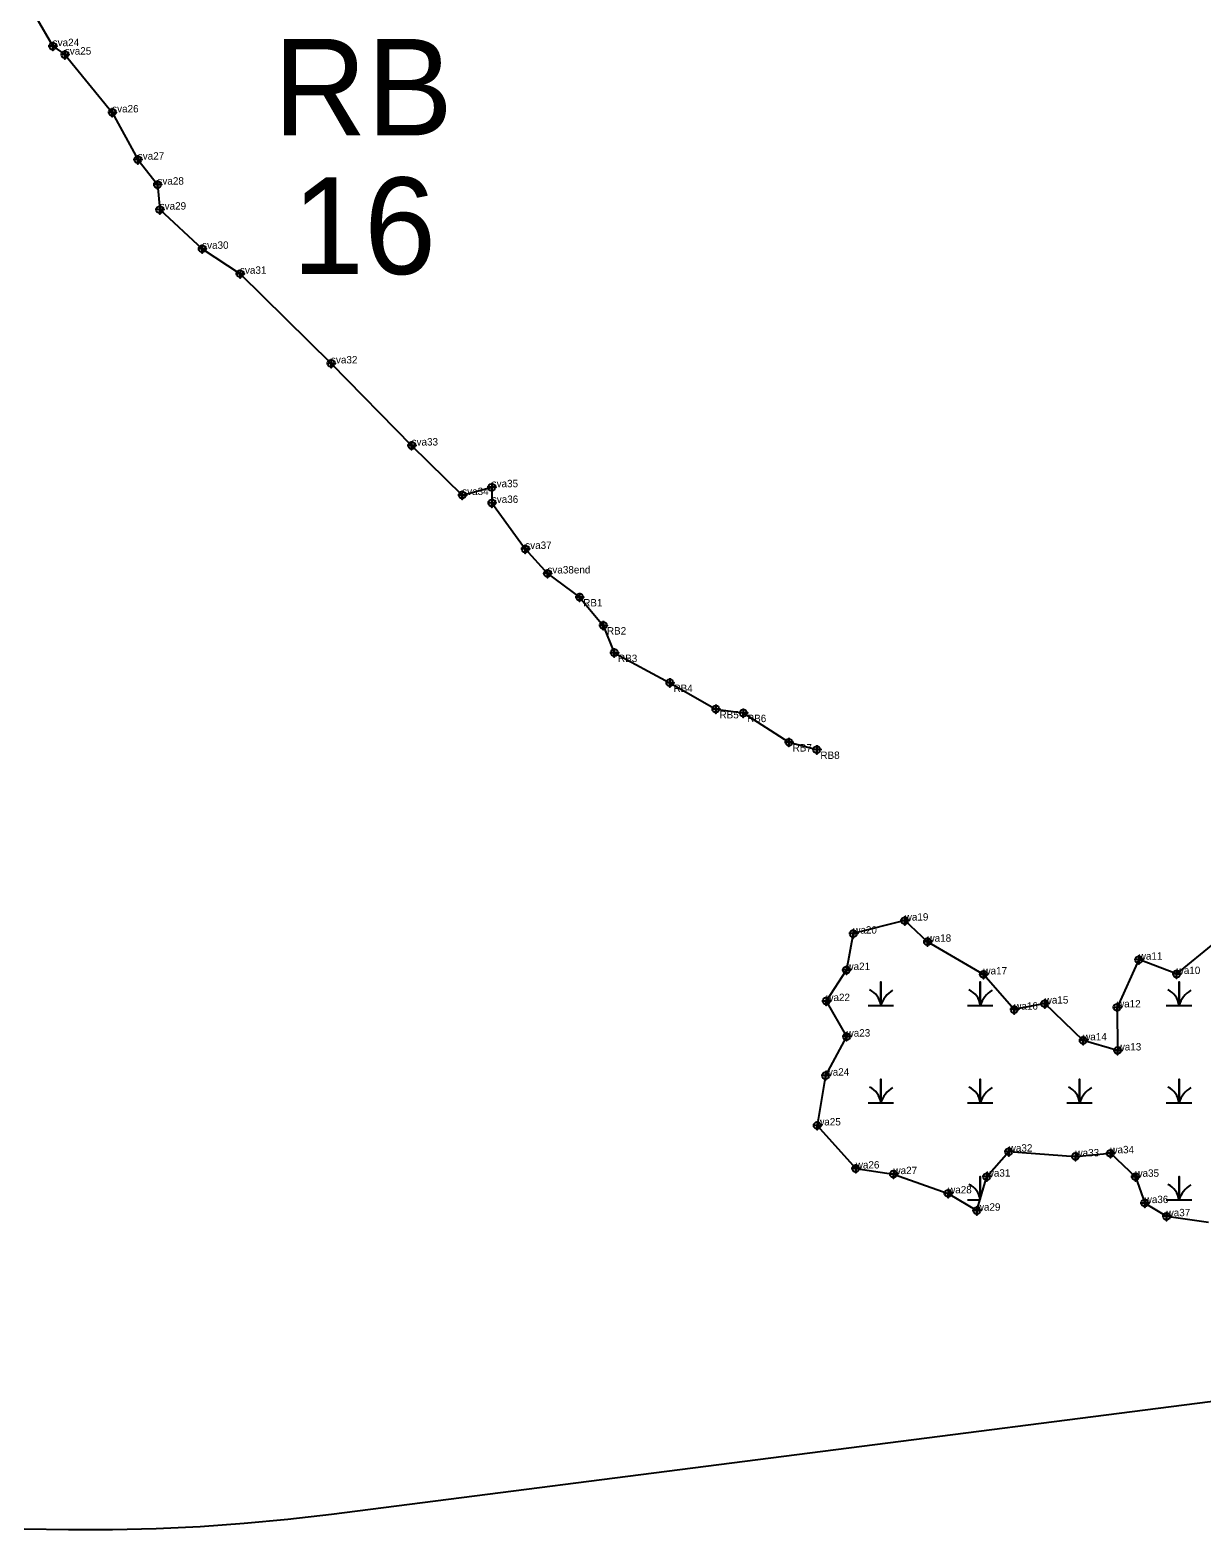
# Model space of a CAD drawing. Extents: x 2071991 to 2268989, y 436479 to 469629.
# Drawn here: x 2212061 to 2212853, y 439006 to 440020 of the extents above; entities that cross this region are included whole.
import ezdxf

# ---------------------------------------------------------------- set-up
doc = ezdxf.new("R2010")
doc.units = 0
for name, color, linetype in [('approx_PSA', 7, 'Continuous'), ('Default', 7, 'Continuous'), ('Exist Environmental Wetland Boundary', 7, 'Continuous'), ('Exist Environmental Wetland Boundary Cogo Comment', 7, 'Continuous'), ('Exist Environmental Wetland Boundary Cogo Point CELL', 7, 'Continuous'), ('Exist Hydro Jurisdictional Stream or Body of Water NEU Mitigable', 7, 'Continuous'), ('Exist Hydro Jurisdictional Stream or Body of Water NEU Mitigable Cogo Comment', 7, 'Continuous'), ('Exist Hydro Jurisdictional Stream or Body of Water NEU Mitigable Cogo Point CELL', 7, 'Continuous'), ('Exist Hydro Swamp or Marsh', 7, 'Continuous')]:
    doc.layers.add(name, color=color, linetype=linetype)

msp = doc.modelspace()

# ---------------------------------------------------------------- linework, layer by layer
at = {"layer": 'approx_PSA'}
for p, q in [((2212901.9, 439098.2), (2212264.6, 439016.5)), ((2212235.1, 439013), (2212205.5, 439010.3)), ((2212264.6, 439016.5), (2212235.1, 439013)), ((2212086.7, 439006), (2212056.9, 439006.6)), ((2212116.4, 439006), (2212086.7, 439006)), ((2212146.1, 439006.8), (2212116.4, 439006)), ((2212175.8, 439008.2), (2212146.1, 439006.8)), ((2212205.5, 439010.3), (2212175.8, 439008.2))]:
    msp.add_line(p, q, dxfattribs=at)
at = {"layer": 'Exist Environmental Wetland Boundary'}
msp.add_lwpolyline([(2212861.6, 439403.2), (2212835.8, 439381.9), (2212810.2, 439391.6), (2212795.5, 439359.3), (2212795.9, 439330.2), (2212772.6, 439337), (2212746.6, 439361.9), (2212726, 439357.8), (2212705.2, 439381.6), (2212667.4, 439403.7), (2212652, 439418), (2212617.2, 439409.2), (2212612.6, 439384.6), (2212599, 439363.6), (2212612.7, 439339.6), (2212598.5, 439313.2), (2212592.8, 439279.5), (2212618.9, 439250.4), (2212644.4, 439246.6), (2212681.3, 439233.6), (2212700.7, 439221.9), (2212707.4, 439244.9), (2212722.3, 439261.8), (2212767.4, 439258.6), (2212791, 439260.7), (2212807.9, 439244.8), (2212814.2, 439227), (2212829, 439218.1), (2212857.3, 439214.2)], dxfattribs=at)
at = {"layer": 'Exist Environmental Wetland Boundary Cogo Point CELL'}
for points in [[(2212652, 439421), (2212652, 439415), (2212652, 439418), (2212655, 439418), (2212649, 439418)], [(2212617.2, 439412.2), (2212617.2, 439406.2), (2212617.2, 439409.2), (2212620.2, 439409.2), (2212614.2, 439409.2)], [(2212667.4, 439406.7), (2212667.4, 439400.7), (2212667.4, 439403.7), (2212670.4, 439403.7), (2212664.4, 439403.7)], [(2212612.6, 439387.6), (2212612.6, 439381.6), (2212612.6, 439384.6), (2212615.6, 439384.6), (2212609.6, 439384.6)], [(2212810.2, 439394.6), (2212810.2, 439388.6), (2212810.2, 439391.6), (2212813.2, 439391.6), (2212807.2, 439391.6)], [(2212705.2, 439384.6), (2212705.2, 439378.6), (2212705.2, 439381.6), (2212708.2, 439381.6), (2212702.2, 439381.6)], [(2212835.8, 439384.9), (2212835.8, 439378.9), (2212835.8, 439381.9), (2212838.8, 439381.9), (2212832.8, 439381.9)], [(2212599, 439366.6), (2212599, 439360.6), (2212599, 439363.6), (2212602, 439363.6), (2212596, 439363.6)], [(2212726, 439360.8), (2212726, 439354.8), (2212726, 439357.8), (2212729, 439357.8), (2212723, 439357.8)], [(2212746.6, 439364.9), (2212746.6, 439358.9), (2212746.6, 439361.9), (2212749.6, 439361.9), (2212743.6, 439361.9)], [(2212795.5, 439362.3), (2212795.5, 439356.3), (2212795.5, 439359.3), (2212798.5, 439359.3), (2212792.5, 439359.3)], [(2212612.7, 439342.6), (2212612.7, 439336.6), (2212612.7, 439339.6), (2212615.7, 439339.6), (2212609.7, 439339.6)], [(2212772.6, 439340), (2212772.6, 439334), (2212772.6, 439337), (2212775.6, 439337), (2212769.6, 439337)], [(2212795.9, 439333.2), (2212795.9, 439327.2), (2212795.9, 439330.2), (2212798.9, 439330.2), (2212792.9, 439330.2)], [(2212598.5, 439316.2), (2212598.5, 439310.2), (2212598.5, 439313.2), (2212601.5, 439313.2), (2212595.5, 439313.2)], [(2212592.8, 439282.5), (2212592.8, 439276.5), (2212592.8, 439279.5), (2212595.8, 439279.5), (2212589.8, 439279.5)], [(2212722.3, 439264.8), (2212722.3, 439258.8), (2212722.3, 439261.8), (2212725.3, 439261.8), (2212719.3, 439261.8)], [(2212767.4, 439261.6), (2212767.4, 439255.6), (2212767.4, 439258.6), (2212770.4, 439258.6), (2212764.4, 439258.6)], [(2212791, 439263.7), (2212791, 439257.7), (2212791, 439260.7), (2212794, 439260.7), (2212788, 439260.7)], [(2212618.9, 439253.4), (2212618.9, 439247.4), (2212618.9, 439250.4), (2212621.9, 439250.4), (2212615.9, 439250.4)], [(2212644.4, 439249.6), (2212644.4, 439243.6), (2212644.4, 439246.6), (2212647.4, 439246.6), (2212641.4, 439246.6)], [(2212707.4, 439247.9), (2212707.4, 439241.9), (2212707.4, 439244.9), (2212710.4, 439244.9), (2212704.4, 439244.9)], [(2212807.9, 439247.8), (2212807.9, 439241.8), (2212807.9, 439244.8), (2212810.9, 439244.8), (2212804.9, 439244.8)], [(2212681.3, 439236.6), (2212681.3, 439230.6), (2212681.3, 439233.6), (2212684.3, 439233.6), (2212678.3, 439233.6)], [(2212700.7, 439224.9), (2212700.7, 439218.9), (2212700.7, 439221.9), (2212703.7, 439221.9), (2212697.7, 439221.9)], [(2212814.2, 439230), (2212814.2, 439224), (2212814.2, 439227), (2212817.2, 439227), (2212811.2, 439227)], [(2212829, 439221.1), (2212829, 439215.1), (2212829, 439218.1), (2212832, 439218.1), (2212826, 439218.1)]]:
    msp.add_lwpolyline(points, dxfattribs=at)
for centre in [(2212652, 439418), (2212617.2, 439409.2), (2212667.4, 439403.7), (2212612.6, 439384.6), (2212810.2, 439391.6), (2212705.2, 439381.6), (2212835.8, 439381.9), (2212599, 439363.6), (2212726, 439357.8), (2212746.6, 439361.9), (2212795.5, 439359.3), (2212612.7, 439339.6), (2212772.6, 439337), (2212795.9, 439330.2), (2212598.5, 439313.2), (2212592.8, 439279.5), (2212722.3, 439261.8), (2212767.4, 439258.6), (2212791, 439260.7), (2212618.9, 439250.4), (2212644.4, 439246.6), (2212707.4, 439244.9), (2212807.9, 439244.8), (2212681.3, 439233.6), (2212700.7, 439221.9), (2212814.2, 439227), (2212829, 439218.1)]:
    msp.add_circle(centre, 2.34, dxfattribs=at)
at = {"layer": 'Exist Hydro Jurisdictional Stream or Body of Water NEU Mitigable'}
for points in [[(2212064.6, 440029), (2212076.1, 440009.2), (2212084.3, 440003.5), (2212116.3, 439964.4), (2212133.6, 439932.5), (2212146.9, 439915.6), (2212148.4, 439898.7), (2212177.1, 439872.2), (2212202.7, 439855.3), (2212264.2, 439794.7), (2212318.7, 439739.2), (2212352.9, 439705.7), (2212372.8, 439711), (2212372.9, 439700.4), (2212395.5, 439669.3), (2212410.5, 439652.7)], [(2212410.5, 439652.7), (2212432.2, 439636.7), (2212448.2, 439617.6), (2212455.7, 439599.1), (2212493.2, 439578.8), (2212524.3, 439561), (2212542.9, 439558.4), (2212573.7, 439538.6), (2212592.5, 439533.6)]]:
    msp.add_lwpolyline(points, dxfattribs=at)
at = {"layer": 'Exist Hydro Jurisdictional Stream or Body of Water NEU Mitigable Cogo Point CELL'}
for points in [[(2212076.1, 440012.2), (2212076.1, 440006.2), (2212076.1, 440009.2), (2212079.1, 440009.2), (2212073.1, 440009.2)], [(2212084.3, 440006.5), (2212084.3, 440000.5), (2212084.3, 440003.5), (2212087.3, 440003.5), (2212081.3, 440003.5)], [(2212116.3, 439967.4), (2212116.3, 439961.4), (2212116.3, 439964.4), (2212119.3, 439964.4), (2212113.3, 439964.4)], [(2212133.6, 439935.5), (2212133.6, 439929.5), (2212133.6, 439932.5), (2212136.6, 439932.5), (2212130.6, 439932.5)], [(2212146.9, 439918.6), (2212146.9, 439912.6), (2212146.9, 439915.6), (2212149.9, 439915.6), (2212143.9, 439915.6)], [(2212148.4, 439901.7), (2212148.4, 439895.7), (2212148.4, 439898.7), (2212151.4, 439898.7), (2212145.4, 439898.7)], [(2212177.1, 439875.2), (2212177.1, 439869.2), (2212177.1, 439872.2), (2212180.1, 439872.2), (2212174.1, 439872.2)], [(2212202.7, 439858.3), (2212202.7, 439852.3), (2212202.7, 439855.3), (2212205.7, 439855.3), (2212199.7, 439855.3)], [(2212264.2, 439797.7), (2212264.2, 439791.7), (2212264.2, 439794.7), (2212267.2, 439794.7), (2212261.2, 439794.7)], [(2212318.7, 439742.2), (2212318.7, 439736.2), (2212318.7, 439739.2), (2212321.7, 439739.2), (2212315.7, 439739.2)], [(2212372.8, 439714), (2212372.8, 439708), (2212372.8, 439711), (2212375.8, 439711), (2212369.8, 439711)], [(2212352.9, 439708.7), (2212352.9, 439702.7), (2212352.9, 439705.7), (2212355.9, 439705.7), (2212349.9, 439705.7)], [(2212372.9, 439703.4), (2212372.9, 439697.4), (2212372.9, 439700.4), (2212375.9, 439700.4), (2212369.9, 439700.4)], [(2212395.5, 439672.3), (2212395.5, 439666.3), (2212395.5, 439669.3), (2212398.5, 439669.3), (2212392.5, 439669.3)], [(2212410.5, 439655.7), (2212410.5, 439649.7), (2212410.5, 439652.7), (2212413.5, 439652.7), (2212407.5, 439652.7)], [(2212432.2, 439639.7), (2212432.2, 439633.7), (2212432.2, 439636.7), (2212435.2, 439636.7), (2212429.2, 439636.7)], [(2212448.2, 439620.6), (2212448.2, 439614.6), (2212448.2, 439617.6), (2212451.2, 439617.6), (2212445.2, 439617.6)], [(2212455.7, 439602.1), (2212455.7, 439596.1), (2212455.7, 439599.1), (2212458.7, 439599.1), (2212452.7, 439599.1)], [(2212493.2, 439581.8), (2212493.2, 439575.8), (2212493.2, 439578.8), (2212496.2, 439578.8), (2212490.2, 439578.8)], [(2212524.3, 439564), (2212524.3, 439558), (2212524.3, 439561), (2212527.3, 439561), (2212521.3, 439561)], [(2212542.9, 439561.4), (2212542.9, 439555.4), (2212542.9, 439558.4), (2212545.9, 439558.4), (2212539.9, 439558.4)], [(2212573.7, 439541.6), (2212573.7, 439535.6), (2212573.7, 439538.6), (2212576.7, 439538.6), (2212570.7, 439538.6)], [(2212592.5, 439536.6), (2212592.5, 439530.6), (2212592.5, 439533.6), (2212595.5, 439533.6), (2212589.5, 439533.6)]]:
    msp.add_lwpolyline(points, dxfattribs=at)
for centre in [(2212076.1, 440009.2), (2212084.3, 440003.5), (2212116.3, 439964.4), (2212133.6, 439932.5), (2212146.9, 439915.6), (2212148.4, 439898.7), (2212177.1, 439872.2), (2212202.7, 439855.3), (2212264.2, 439794.7), (2212318.7, 439739.2), (2212372.8, 439711), (2212352.9, 439705.7), (2212372.9, 439700.4), (2212395.5, 439669.3), (2212410.5, 439652.7), (2212432.2, 439636.7), (2212448.2, 439617.6), (2212455.7, 439599.1), (2212493.2, 439578.8), (2212524.3, 439561), (2212542.9, 439558.4), (2212573.7, 439538.6), (2212592.5, 439533.6)]:
    msp.add_circle(centre, 2.34, dxfattribs=at)
at = {"layer": 'Exist Hydro Swamp or Marsh'}
msp.add_line((2212694.4, 439229.1), (2212702.8, 439229.1), dxfattribs=at)
for points in [[(2212627.2, 439360.7), (2212635.8, 439360.7), (2212635.8, 439376.5), (2212635.8, 439360.7), (2212644.4, 439360.7)], [(2212694.4, 439360.7), (2212703, 439360.7), (2212703, 439376.5), (2212703, 439360.7), (2212711.6, 439360.7)], [(2212828.8, 439360.7), (2212837.4, 439360.7), (2212837.4, 439376.5), (2212837.4, 439360.7), (2212846, 439360.7)], [(2212627.2, 439294.9), (2212635.8, 439294.9), (2212635.8, 439310.7), (2212635.8, 439294.9), (2212644.4, 439294.9)], [(2212694.4, 439294.9), (2212703, 439294.9), (2212703, 439310.7), (2212703, 439294.9), (2212711.6, 439294.9)], [(2212761.6, 439294.9), (2212770.2, 439294.9), (2212770.2, 439310.7), (2212770.2, 439294.9), (2212778.8, 439294.9)], [(2212828.8, 439294.9), (2212837.4, 439294.9), (2212837.4, 439310.7), (2212837.4, 439294.9), (2212846, 439294.9)], [(2212703, 439229.7), (2212703, 439244.9), (2212703, 439229.7)], [(2212828.8, 439229.1), (2212837.4, 439229.1), (2212837.4, 439244.9), (2212837.4, 439229.1), (2212846, 439229.1)]]:
    msp.add_lwpolyline(points, dxfattribs=at)
for centre, radius, start, end in [((2212623.5, 439359.8), 12.3, 4.1403, 67.535), ((2212654, 439354.6), 19.2, 122.1274, 161.6222), ((2212690.7, 439359.8), 12.3, 4.1403, 67.535), ((2212721.2, 439354.6), 19.2, 122.1274, 161.6222), ((2212825.1, 439359.8), 12.3, 4.1403, 67.535), ((2212855.6, 439354.6), 19.2, 122.1274, 161.6222), ((2212623.5, 439294), 12.3, 4.1403, 67.535), ((2212690.7, 439294), 12.3, 4.1403, 67.535), ((2212757.9, 439294), 12.3, 4.1403, 67.535), ((2212825.1, 439294), 12.3, 4.1403, 67.535), ((2212654, 439288.8), 19.2, 122.1274, 161.6222), ((2212721.2, 439288.8), 19.2, 122.1274, 161.6222), ((2212788.4, 439288.8), 19.2, 122.1274, 161.6222), ((2212855.6, 439288.8), 19.2, 122.1274, 161.6222), ((2212690.7, 439228.2), 12.3, 6.2272, 67.535), ((2212825.1, 439228.2), 12.3, 4.1403, 67.535), ((2212855.6, 439223.1), 19.2, 122.1274, 161.6222)]:
    msp.add_arc(centre, radius, start, end, dxfattribs=at)

# ---------------------------------------------------------------- texts
at = {"layer": 'Default'}
for s, p in [('RB', (2212225.2, 439948.8)), ('RB', (2212225.2, 439948.8)), ('16', (2212238, 439855.1))]:
    msp.add_text(s, height=65.34, dxfattribs=at).set_placement(p)
at = {"layer": 'Exist Environmental Wetland Boundary Cogo Comment'}
for s, p in [('wa19', (2212652, 439418)), ('wa20', (2212617.2, 439409.2)), ('wa18', (2212667.4, 439403.7)), ('wa21', (2212612.6, 439384.6)), ('wa17', (2212705.2, 439381.6)), ('wa11', (2212810.2, 439391.6)), ('wa10', (2212835.8, 439381.9)), ('wa22', (2212599, 439363.6)), ('wa15', (2212746.6, 439361.9)), ('wa16', (2212726, 439357.8)), ('wa12', (2212795.5, 439359.3)), ('wa23', (2212612.7, 439339.6)), ('wa14', (2212772.6, 439337)), ('wa13', (2212795.9, 439330.2)), ('wa24', (2212598.5, 439313.2)), ('wa25', (2212592.8, 439279.5)), ('wa32', (2212722.3, 439261.8)), ('wa34', (2212791, 439260.7)), ('wa26', (2212618.9, 439250.4)), ('wa33', (2212767.4, 439258.6)), ('wa27', (2212644.4, 439246.6)), ('wa31', (2212707.4, 439244.9)), ('wa35', (2212807.9, 439244.8)), ('wa28', (2212681.3, 439233.6)), ('wa29', (2212700.7, 439221.9)), ('wa36', (2212814.2, 439227)), ('wa37', (2212829, 439218.1))]:
    msp.add_text(s, height=5, dxfattribs=at).set_placement(p)
at = {"layer": 'Exist Hydro Jurisdictional Stream or Body of Water NEU Mitigable Cogo Comment'}
for s, p in [('sva24', (2212076.1, 440009.2)), ('sva25', (2212084.3, 440003.5)), ('sva26', (2212116.3, 439964.4)), ('sva27', (2212133.6, 439932.5)), ('sva28', (2212146.9, 439915.6)), ('sva29', (2212148.4, 439898.7)), ('sva30', (2212177.1, 439872.2)), ('sva31', (2212202.7, 439855.3)), ('sva32', (2212264.2, 439794.7)), ('sva33', (2212318.7, 439739.2)), ('sva35', (2212372.8, 439711)), ('sva34', (2212352.9, 439705.7)), ('sva36', (2212372.9, 439700.4)), ('sva37', (2212395.5, 439669.3)), ('sva38end', (2212410.5, 439652.7)), ('RB1', (2212434.7, 439630.4)), ('RB2', (2212450.7, 439611.4)), ('RB3', (2212458.2, 439592.8)), ('RB4', (2212495.7, 439572.6)), ('RB5', (2212526.8, 439554.7)), ('RB6', (2212545.4, 439552.2)), ('RB7', (2212576.2, 439532.3)), ('RB8', (2212595, 439527.3))]:
    msp.add_text(s, height=5, dxfattribs=at).set_placement(p)

doc.saveas('drawing.dxf')
